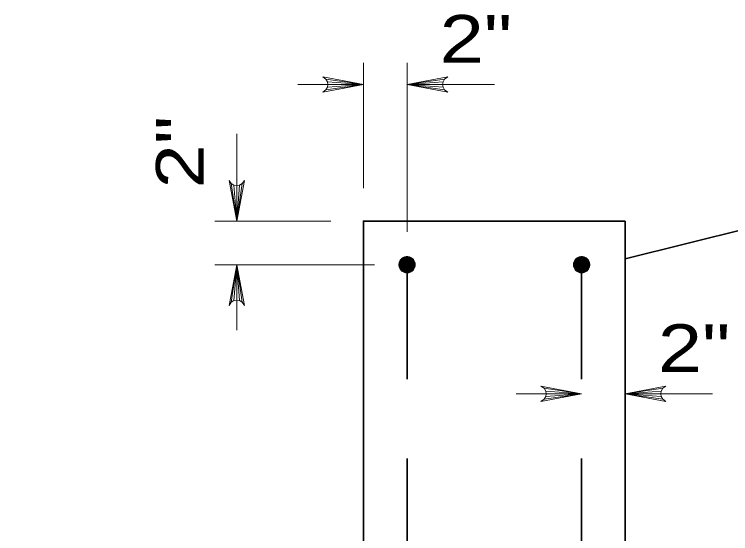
# Model space of a CAD drawing. Extents: x 394.95 to 401.96, y -76.51 to -66.78.
# Drawn here: x 399.389 to 400.292, y -67.52 to -66.866 of the extents above; entities that cross this region are included whole.
import ezdxf
from ezdxf.enums import TextEntityAlignment as Align

# ---------------------------------------------------------------- set-up
doc = ezdxf.new("R2010")
doc.units = 0
doc.header["$LTSCALE"] = 0.024
doc.linetypes.add('LONG_DASHED', pattern=[7.5, 6, -1.5])
doc.layers.add('1', color=7, linetype='LONG_DASHED', lineweight=35)
doc.layers.add('10', color=7, linetype='Continuous', lineweight=13)
doc.layers.add('12', color=7, linetype='Continuous')

msp = doc.modelspace()

# ---------------------------------------------------------------- linework, layer by layer
at = {"layer": '1', "linetype": 'Continuous'}
for p, q in [((400.15918, -67.17381), (401.07785, -66.94648)), ((400.15918, -67.6764), (400.15918, -67.1264))]:
    msp.add_line(p, q, dxfattribs=at)
at = {"layer": '1'}
for p, q in [((399.88418, -67.1814), (399.88418, -67.9239)), ((400.10418, -67.1814), (400.10418, -67.9239))]:
    msp.add_line(p, q, dxfattribs=at)
at = {"layer": '1', "linetype": 'Continuous'}
msp.add_lwpolyline([(399.38918, -68.0064), (399.38918, -67.6764), (399.82918, -67.6764), (399.82918, -67.1264), (400.15918, -67.1264)], dxfattribs=at)
at = {"layer": '1', "lineweight": 13}
for points in [[(399.88144, -67.17184), (399.88465, -67.17128), (399.88843, -67.17241), (399.89241, -67.1759), (399.8938, -67.17923), (399.89384, -67.18324), (399.89175, -67.18774), (399.88875, -67.1904), (399.88542, -67.19123), (399.88165, -67.19111), (399.8784, -67.18954), (399.87618, -67.18749), (399.87478, -67.18442), (399.87412, -67.18095), (399.87498, -67.17774), (399.87658, -67.17502), (399.8792, -67.17285), (399.88144, -67.17193), (399.8873, -67.17197), (399.88027, -67.17236), (399.88867, -67.17241), (399.87843, -67.17297), (399.88982, -67.17317), (399.87795, -67.1736), (399.89047, -67.17369), (399.87727, -67.17414), (399.89127, -67.17437), (399.87662, -67.17473), (399.89187, -67.17489), (399.8763, -67.17533), (399.89211, -67.17542), (399.87585, -67.17577), (399.89268, -67.1759), (399.87561, -67.17609), (399.89284, -67.17637), (399.87543, -67.17663), (399.89312, -67.17675), (399.87522, -67.17702), (399.89336, -67.17718), (399.87466, -67.17758), (399.89353, -67.17758), (399.87457, -67.17819), (399.89365, -67.17791), (399.87445, -67.17886), (399.89384, -67.17854), (399.87421, -67.17964), (399.89389, -67.17907), (399.87433, -67.17931), (399.89412, -67.17955), (399.87418, -67.18011), (399.89409, -67.18007), (399.87409, -67.18055), (399.89421, -67.18047), (399.87405, -67.181), (399.89421, -67.18083), (399.87418, -67.18164), (399.89421, -67.18132), (399.87409, -67.18212), (399.89433, -67.18183), (399.87401, -67.18135), (399.89421, -67.18228), (399.87412, -67.18252), (399.89428, -67.18273), (399.87418, -67.18297), (399.89409, -67.18321), (399.87425, -67.18336), (399.89396, -67.18361), (399.87442, -67.18389), (399.89389, -67.18397), (399.8745, -67.18433), (399.8938, -67.18445), (399.87481, -67.18484), (399.89372, -67.1849), (399.8749, -67.18529), (399.89353, -67.18522), (399.87502, -67.18577), (399.89329, -67.18561), (399.87534, -67.18621), (399.89316, -67.18609), (399.87558, -67.18661), (399.89289, -67.18653), (399.8757, -67.18698), (399.8926, -67.18706), (399.87602, -67.18738), (399.89235, -67.18742), (399.87634, -67.1877), (399.89192, -67.1879), (399.87682, -67.18823), (399.89135, -67.18839), (399.8773, -67.18879), (399.89075, -67.18891), (399.87799, -67.18947), (399.89031, -67.1893), (399.87923, -67.1901), (399.88987, -67.18986), (399.87887, -67.18986), (399.88919, -67.19023), (399.87968, -67.1904), (399.8883, -67.19067), (399.88031, -67.19072), (399.8873, -67.19103)], [(399.8873, -67.19103), (399.88373, -67.19147), (399.87843, -67.18802), (399.87519, -67.18092), (399.87995, -67.17289), (399.88691, -67.17205), (399.89228, -67.17823), (399.89228, -67.18484), (399.88891, -67.18975), (399.88333, -67.19083), (399.87703, -67.18754), (399.87931, -67.18943), (399.8753, -67.17892), (399.87906, -67.17309), (399.88461, -67.17149), (399.88871, -67.17333), (399.89216, -67.17734), (399.89369, -67.18064), (399.89187, -67.18709)], [(400.10692, -67.17184), (400.10371, -67.17128), (400.09994, -67.17241), (400.09596, -67.1759), (400.09455, -67.17923), (400.09452, -67.18324), (400.0966, -67.18774), (400.0996, -67.1904), (400.10294, -67.19123), (400.10672, -67.19111), (400.10997, -67.18954), (400.11218, -67.18749), (400.11358, -67.18442), (400.11423, -67.18095), (400.11337, -67.17774), (400.11177, -67.17502), (400.10917, -67.17285), (400.10692, -67.17193), (400.10106, -67.17197), (400.10808, -67.17236), (400.09969, -67.17241), (400.10993, -67.17297), (400.09853, -67.17317), (400.11041, -67.1736), (400.09789, -67.17369), (400.11108, -67.17414), (400.09708, -67.17437), (400.11174, -67.17473), (400.09648, -67.17489), (400.11206, -67.17533), (400.09624, -67.17542), (400.1125, -67.17577), (400.09568, -67.1759), (400.11274, -67.17609), (400.09551, -67.17637), (400.11295, -67.17663), (400.09524, -67.17675), (400.11314, -67.17702), (400.095, -67.17718), (400.1137, -67.17758), (400.09484, -67.17758), (400.11378, -67.17819), (400.09471, -67.17791), (400.11391, -67.17886), (400.09452, -67.17854), (400.11415, -67.17964), (400.09447, -67.17907), (400.11402, -67.17931), (400.09423, -67.17955), (400.11418, -67.18011), (400.09428, -67.18007), (400.11426, -67.18055), (400.09416, -67.18047), (400.1143, -67.181), (400.09416, -67.18083), (400.11418, -67.18164), (400.09416, -67.18132), (400.11426, -67.18212), (400.09402, -67.18183), (400.11434, -67.18135), (400.09416, -67.18228), (400.11423, -67.18252), (400.09407, -67.18273), (400.11418, -67.18297), (400.09428, -67.18321), (400.1141, -67.18336), (400.0944, -67.18361), (400.11394, -67.18389), (400.09447, -67.18397), (400.11386, -67.18433), (400.09455, -67.18445), (400.11354, -67.18484), (400.09464, -67.1849), (400.11346, -67.18529), (400.09484, -67.18522), (400.11334, -67.18577), (400.09508, -67.18561), (400.11302, -67.18621), (400.0952, -67.18609), (400.11278, -67.18661), (400.09548, -67.18653), (400.11266, -67.18698), (400.09576, -67.18706), (400.11233, -67.18738), (400.096, -67.18742), (400.11201, -67.1877), (400.09645, -67.1879), (400.11153, -67.18823), (400.097, -67.18839), (400.11105, -67.18879), (400.0976, -67.18891), (400.11036, -67.18947), (400.09805, -67.1893), (400.10913, -67.1901), (400.09848, -67.18986), (400.10948, -67.18986), (400.09917, -67.19023), (400.10868, -67.1904), (400.10005, -67.19067), (400.10804, -67.19072), (400.10106, -67.19103)], [(400.10106, -67.19103), (400.10462, -67.19147), (400.10993, -67.18802), (400.11319, -67.18092), (400.10841, -67.17289), (400.10146, -67.17205), (400.09607, -67.17823), (400.09607, -67.18484), (400.09945, -67.18975), (400.10502, -67.19083), (400.11132, -67.18754), (400.10905, -67.18943), (400.11306, -67.17892), (400.10929, -67.17309), (400.10374, -67.17149), (400.09966, -67.17333), (400.0962, -67.17734), (400.09468, -67.18064), (400.09648, -67.18709)]]:
    msp.add_lwpolyline(points, dxfattribs=at)
for centre in [(399.88418, -67.1814), (400.10418, -67.1814)]:
    msp.add_circle(centre, 0.01031, dxfattribs=at)
at = {"layer": '10'}
for p, q in [((399.82918, -67.08515), (399.82918, -66.92692)), ((399.88418, -67.14015), (399.88418, -66.92692)), ((399.74668, -66.95442), (399.82918, -66.95442)), ((399.88418, -66.95442), (399.99418, -66.95442)), ((399.66947, -67.0164), (399.66947, -67.1264)), ((399.78793, -67.1264), (399.64197, -67.1264)), ((399.84293, -67.1814), (399.64197, -67.1814)), ((399.66947, -67.1814), (399.66947, -67.2639)), ((400.02168, -67.34395), (400.10418, -67.34395)), ((400.15918, -67.34395), (400.26918, -67.34395))]:
    msp.add_line(p, q, dxfattribs=at)
for points in [[(399.82918, -66.95442), (399.77792, -66.96403), (399.78186, -66.96129), (399.78391, -66.95785), (399.78449, -66.95442), (399.78391, -66.95098), (399.78186, -66.94754), (399.77792, -66.9448), (399.82918, -66.95442), (399.78186, -66.94754), (399.78391, -66.95098), (399.82918, -66.95442), (399.78449, -66.95442), (399.78391, -66.95785), (399.82918, -66.95442), (399.78186, -66.96129)], [(399.88418, -66.95442), (399.93544, -66.9448), (399.93149, -66.94754), (399.92946, -66.95098), (399.92886, -66.95442), (399.92946, -66.95785), (399.93149, -66.96129), (399.93544, -66.96403), (399.88418, -66.95442), (399.93149, -66.96129), (399.92946, -66.95785), (399.88418, -66.95442), (399.92886, -66.95442), (399.92946, -66.95098), (399.88418, -66.95442), (399.93149, -66.94754)], [(399.88418, -66.95442), (399.93544, -66.9448), (399.93149, -66.94754), (399.92946, -66.95098), (399.92886, -66.95442), (399.92946, -66.95785), (399.93149, -66.96129), (399.93544, -66.96403), (399.88418, -66.95442), (399.93149, -66.96129), (399.92946, -66.95785), (399.88418, -66.95442), (399.92886, -66.95442), (399.92946, -66.95098), (399.88418, -66.95442), (399.93149, -66.94754)], [(399.66947, -67.1264), (399.65985, -67.07514), (399.66259, -67.07908), (399.66603, -67.08111), (399.66947, -67.08171), (399.67291, -67.08111), (399.67634, -67.07908), (399.67907, -67.07514), (399.66947, -67.1264), (399.67634, -67.07908), (399.67291, -67.08111), (399.66947, -67.1264), (399.66947, -67.08171), (399.66603, -67.08111), (399.66947, -67.1264), (399.66259, -67.07908)], [(399.66947, -67.1814), (399.67907, -67.23267), (399.67634, -67.22871), (399.67291, -67.22667), (399.66947, -67.22608), (399.66603, -67.22667), (399.66259, -67.22871), (399.65985, -67.23267), (399.66947, -67.1814), (399.66259, -67.22871), (399.66603, -67.22667), (399.66947, -67.1814), (399.66947, -67.22608), (399.67291, -67.22667), (399.66947, -67.1814), (399.67634, -67.22871)], [(400.10418, -67.34395), (400.05292, -67.35356), (400.05686, -67.35082), (400.05891, -67.34739), (400.05949, -67.34395), (400.05891, -67.34051), (400.05686, -67.33707), (400.05292, -67.33433), (400.10418, -67.34395), (400.05686, -67.33707), (400.05891, -67.34051), (400.10418, -67.34395), (400.05949, -67.34395), (400.05891, -67.34739), (400.10418, -67.34395), (400.05686, -67.35082)], [(400.15918, -67.34395), (400.21044, -67.33433), (400.20649, -67.33707), (400.20446, -67.34051), (400.20386, -67.34395), (400.20446, -67.34739), (400.20649, -67.35082), (400.21044, -67.35356), (400.15918, -67.34395), (400.20649, -67.35082), (400.20446, -67.34739), (400.15918, -67.34395), (400.20386, -67.34395), (400.20446, -67.34051), (400.15918, -67.34395), (400.20649, -67.33707)], [(400.15918, -67.34395), (400.21044, -67.33433), (400.20649, -67.33707), (400.20446, -67.34051), (400.20386, -67.34395), (400.20446, -67.34739), (400.20649, -67.35082), (400.21044, -67.35356), (400.15918, -67.34395), (400.20649, -67.35082), (400.20446, -67.34739), (400.15918, -67.34395), (400.20386, -67.34395), (400.20446, -67.34051), (400.15918, -67.34395), (400.20649, -67.33707)]]:
    msp.add_lwpolyline(points, dxfattribs=at)

# ---------------------------------------------------------------- texts
at = {"layer": '12', "width": 1.25}
for p in [(399.9709, -66.92691), (400.2459, -67.31644)]:
    msp.add_text('2"', height=0.06, dxfattribs=at).set_placement(p, align=Align.CENTER)
msp.add_text('2"', height=0.06, rotation=90, dxfattribs=at).set_placement((399.6277, -67.03966), align=Align.CENTER)

doc.saveas('drawing.dxf')
